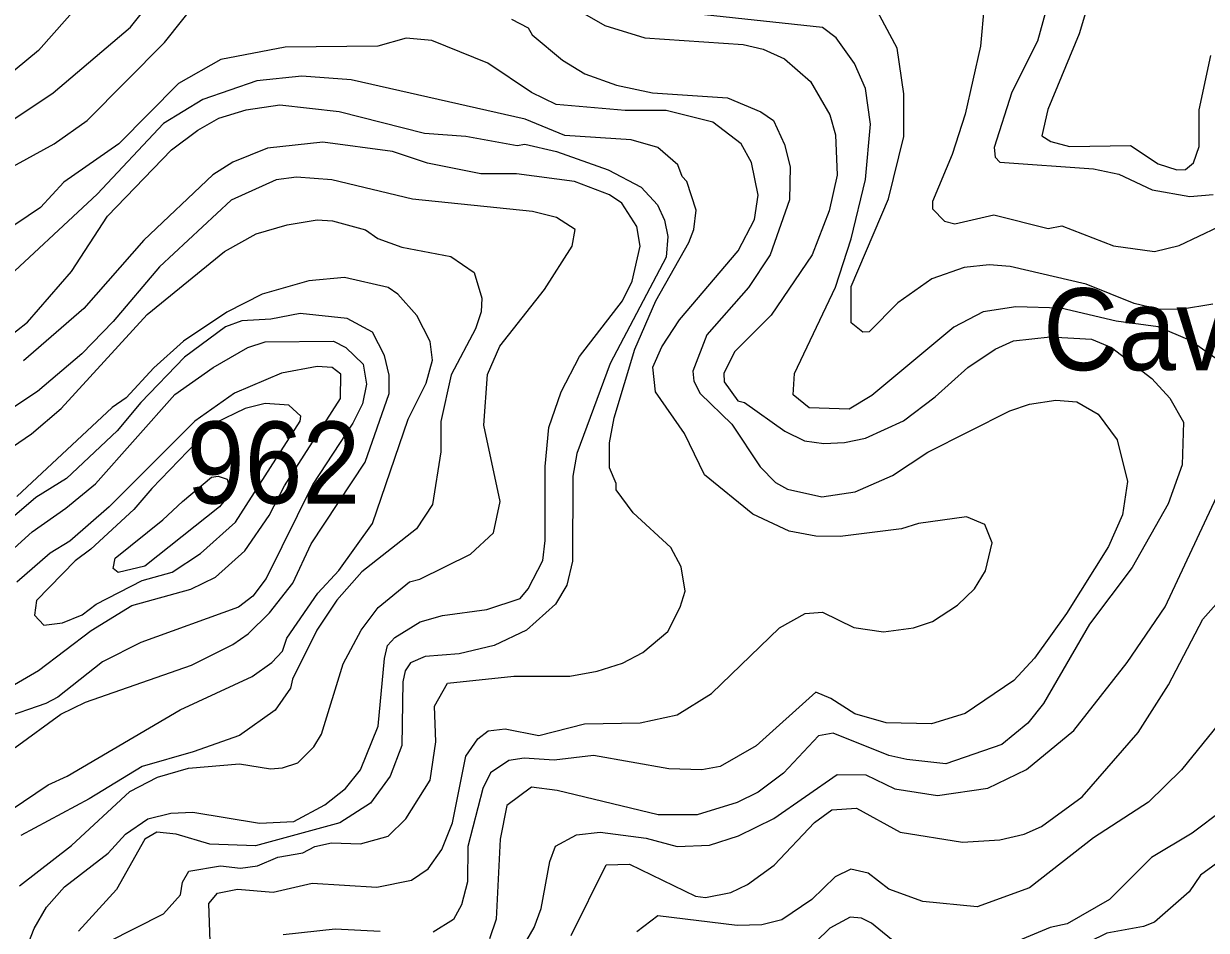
# Model space of a CAD drawing. Extents: x 673.3 to 698.5, y 6984.3 to 7012.3.
# Drawn here: x 686.277 to 687.432, y 6996.366 to 6997.251 of the extents above; entities that cross this region are included whole.
import ezdxf
from ezdxf.enums import TextEntityAlignment as Align

# ---------------------------------------------------------------- set-up
doc = ezdxf.new("R2010")
doc.units = 0
doc.header["$LTSCALE"] = 0.032
doc.layers.add('1', color=7, linetype='Continuous', lineweight=25)
doc.layers.add('2', color=7, linetype='Continuous', lineweight=13)
doc.layers.add('21', color=7, linetype='Continuous')
doc.layers.add('27', color=7, linetype='Continuous')

msp = doc.modelspace()

# ---------------------------------------------------------------- linework, layer by layer
at = {"layer": '1'}
for points in [[(686.1909, 6997.1063), (686.3064, 6997.1831), (686.3819, 6997.2472), (686.4314, 6997.3098)], [(687.323, 6997.2908), (687.3078, 6997.2406), (687.2774, 6997.167), (687.2714, 6997.141), (687.2802, 6997.1355), (687.2986, 6997.1309), (687.358, 6997.1316), (687.385, 6997.1139), (687.4032, 6997.1081), (687.4118, 6997.1084), (687.4195, 6997.1149), (687.425, 6997.1306), (687.4251, 6997.1667), (687.4366, 6997.2195)], [(686.8021, 6997.2733), (686.8448, 6997.2488), (686.8839, 6997.2367), (686.9799, 6997.2304), (686.9994, 6997.2257), (687.0204, 6997.2163), (687.0456, 6997.1943), (687.0644, 6997.1618), (687.0701, 6997.1422), (687.0717, 6997.1028), (687.0639, 6997.068), (687.0473, 6997.0251), (687.0071, 6996.9661), (686.9716, 6996.9305), (686.961, 6996.9091), (686.9615, 6996.901), (686.9748, 6996.8825), (686.9811, 6996.8809), (687.0207, 6996.853), (687.0399, 6996.8435), (687.0588, 6996.841), (687.0787, 6996.8417), (687.0993, 6996.8461), (687.1363, 6996.8631), (687.1674, 6996.8865), (687.1993, 6996.915), (687.2259, 6996.9331), (687.2438, 6996.9412), (687.2796, 6996.9451), (687.3201, 6996.9427), (687.3394, 6996.9347), (687.379, 6996.9042), (687.3964, 6996.8852), (687.4097, 6996.8618), (687.4085, 6996.82), (687.3949, 6996.782), (687.3597, 6996.7197), (687.318, 6996.6644), (687.273, 6996.5871), (687.2579, 6996.568), (687.2323, 6996.5471), (687.1777, 6996.5283), (687.1396, 6996.5323), (687.1222, 6996.5365), (687.0679, 6996.5582), (687.0535, 6996.5557), (687.0194, 6996.519), (686.9946, 6996.5007), (686.9741, 6996.4905), (686.935, 6996.4785), (686.8969, 6996.4785), (686.7982, 6996.5023), (686.7731, 6996.5054), (686.7492, 6996.4875), (686.7427, 6996.4546), (686.7386, 6996.3767), (686.7321, 6996.3573)], [(686.7866, 6996.8184), (686.7901, 6996.8564), (686.8021, 6996.8914), (686.8202, 6996.9259), (686.862, 6996.98), (686.8715, 6996.9992), (686.8794, 6997.0334), (686.8762, 6997.0526), (686.8613, 6997.0756), (686.8493, 6997.0836), (686.8153, 6997.0966), (686.7585, 6997.104), (686.7237, 6997.104), (686.6716, 6997.1146), (686.6376, 6997.1259), (686.5695, 6997.1349), (686.5155, 6997.1292), (686.4816, 6997.1156), (686.4623, 6997.1031), (686.3947, 6997.0394), (686.3361, 6996.9726), (686.2772, 6996.9217)], [(686.2535, 6996.7256), (686.2858, 6996.7545), (686.3187, 6996.7776), (686.3475, 6996.8016), (686.4249, 6996.8887), (686.4625, 6996.915), (686.4962, 6996.9347), (686.5132, 6996.94), (686.5801, 6996.9406), (686.592, 6996.9346), (686.609, 6996.9182), (686.6123, 6996.8989), (686.6082, 6996.8797), (686.5987, 6996.8608), (686.5598, 6996.8011), (686.5141, 6996.709), (686.5012, 6996.6918), (686.4873, 6996.681), (686.392, 6996.6468), (686.3545, 6996.6277), (686.3109, 6996.5932), (686.2992, 6996.587), (686.2558, 6996.5721)], [(686.2788, 6996.3449), (686.2878, 6996.3676), (686.2999, 6996.3884), (686.3174, 6996.4083), (686.3599, 6996.4411), (686.3768, 6996.4596), (686.3986, 6996.4745), (686.421, 6996.4801), (686.4425, 6996.4809), (686.5076, 6996.4704), (686.5411, 6996.4719), (686.5714, 6996.4882), (686.5918, 6996.5043), (686.6062, 6996.5225), (686.6236, 6996.5649), (686.6296, 6996.6311), (686.6328, 6996.6438), (686.6397, 6996.6515), (686.6645, 6996.6669), (686.6865, 6996.6731), (686.7298, 6996.6787), (686.7622, 6996.6895), (686.7701, 6996.6991), (686.7844, 6996.7268), (686.7867, 6996.7461), (686.7866, 6996.8184)], [(687.4624, 6996.4458), (687.4265, 6996.4195), (687.4152, 6996.4033), (687.3815, 6996.3737), (687.3709, 6996.3695), (687.335, 6996.363), (687.3171, 6996.3541), (687.271, 6996.3195), (687.2383, 6996.3007), (687.2079, 6996.2955), (687.1673, 6996.2977), (687.1335, 6996.312), (687.1129, 6996.3295), (687.1084, 6996.3305), (687.1066, 6996.3342), (687.0973, 6996.334), (687.0789, 6996.318)]]:
    msp.add_lwpolyline(points, dxfattribs=at)
at = {"layer": '2'}
for points in [[(686.4192, 6997.3684), (686.2921, 6997.2243), (686.2579, 6997.1961)], [(686.2604, 6997.1075), (686.3073, 6997.1334), (686.3396, 6997.156), (686.415, 6997.2324), (686.4519, 6997.279)], [(687.4534, 6996.9154), (687.4164, 6996.9415), (687.3852, 6996.9549), (687.3441, 6996.9604), (687.2901, 6996.9729), (687.2461, 6996.9744), (687.2143, 6996.9695), (687.1855, 6996.9545), (687.1054, 6996.8876), (687.0835, 6996.8744), (687.0444, 6996.8757), (687.0287, 6996.8883), (687.0301, 6996.9092), (687.0701, 6996.9933), (687.0855, 6997.0405), (687.0993, 6997.0984), (687.1042, 6997.1524), (687.0992, 6997.1873), (687.0886, 6997.2118), (687.0708, 6997.2367), (687.0573, 6997.247), (686.8846, 6997.2655)], [(687.4385, 6996.9768), (687.4069, 6996.9716), (687.3846, 6996.9721), (687.3615, 6996.9775), (687.3149, 6996.9965), (687.2406, 6997.0135), (687.2201, 6997.0152), (687.1956, 6997.0126), (687.164, 6997.0015), (687.1308, 6996.9781), (687.1028, 6996.9497), (687.0968, 6996.9494), (687.0852, 6996.9586), (687.0855, 6996.994), (687.1217, 6997.0798), (687.1368, 6997.1406), (687.1368, 6997.182), (687.1304, 6997.2266), (687.1085, 6997.2674)], [(687.2151, 6997.2685), (687.2117, 6997.2286), (687.1968, 6997.1622), (687.1841, 6997.123), (687.1646, 6997.0771), (687.1646, 6997.0698), (687.1765, 6997.0578), (687.1867, 6997.0552), (687.2245, 6997.064), (687.2777, 6997.0507), (687.2911, 6997.0534), (687.3416, 6997.0339), (687.3814, 6997.0283), (687.4056, 6997.034), (687.4631, 6997.0614)], [(687.2778, 6997.2712), (687.2672, 6997.2337), (687.2423, 6997.1837), (687.225, 6997.1298), (687.2258, 6997.1204), (687.2306, 6997.1155), (687.322, 6997.1088), (687.3468, 6997.1037), (687.3791, 6997.0885), (687.4159, 6997.082), (687.4388, 6997.084)], [(686.7537, 6997.255), (686.7699, 6997.2467), (686.774, 6997.2398), (686.8034, 6997.2149), (686.8252, 6997.2016), (686.8564, 6997.1906), (686.8914, 6997.183), (686.9647, 6997.1781), (686.997, 6997.1645), (687.0096, 6997.1561), (687.0203, 6997.1328), (687.0259, 6997.1109), (687.0253, 6997.0788), (687.0064, 6997.0249), (686.985, 6996.993), (686.9443, 6996.9469), (686.9309, 6996.9114), (686.9316, 6996.9016), (686.9378, 6996.8896), (686.9689, 6996.8599), (686.9965, 6996.818), (687.0114, 6996.8027), (687.0232, 6996.7963), (687.0567, 6996.7889), (687.0894, 6996.7936), (687.1257, 6996.8096), (687.1602, 6996.8323), (687.2403, 6996.8726), (687.2595, 6996.8791), (687.2853, 6996.8833), (687.3057, 6996.8815), (687.3266, 6996.8694), (687.3451, 6996.8445), (687.3551, 6996.8037), (687.3503, 6996.7712), (687.3365, 6996.7402), (687.2956, 6996.6748), (687.2644, 6996.6314), (687.2441, 6996.6094), (687.1966, 6996.5772), (687.1637, 6996.5673), (687.1194, 6996.5681), (687.0888, 6996.577), (687.0654, 6996.5921), (687.0509, 6996.5981), (686.9925, 6996.5459), (686.9574, 6996.5255), (686.9397, 6996.5225), (686.9073, 6996.5234), (686.8338, 6996.5363), (686.7955, 6996.5318), (686.766, 6996.5339), (686.7511, 6996.5314), (686.7333, 6996.5195), (686.7256, 6996.5041), (686.7111, 6996.4474), (686.7109, 6996.4129), (686.7049, 6996.3906), (686.6971, 6996.3762), (686.6772, 6996.3639)], [(686.4602, 6996.3363), (686.4583, 6996.3919), (686.4666, 6996.4019), (686.4862, 6996.406), (686.5211, 6996.4028), (686.5592, 6996.4117), (686.6224, 6996.4077), (686.6562, 6996.4146), (686.6725, 6996.4256), (686.6857, 6996.4445), (686.696, 6996.4706), (686.7092, 6996.5358), (686.7207, 6996.5526), (686.731, 6996.5605), (686.7474, 6996.5624), (686.7803, 6996.5559), (686.8249, 6996.5672), (686.8794, 6996.5681), (686.9156, 6996.576), (686.949, 6996.5968), (687.0155, 6996.6611), (687.0403, 6996.6748), (687.0575, 6996.6764), (687.0878, 6996.6613), (687.117, 6996.6569), (687.1461, 6996.661), (687.1648, 6996.6672), (687.1893, 6996.6831), (687.2058, 6996.6991), (687.2166, 6996.7166), (687.2231, 6996.744), (687.2157, 6996.7619), (687.198, 6996.7692), (687.1511, 6996.7628), (687.1345, 6996.7575), (687.0747, 6996.7501), (687.0508, 6996.7504), (687.0247, 6996.7552), (686.9892, 6996.7718), (686.9421, 6996.8102), (686.9226, 6996.8507), (686.8943, 6996.8912), (686.8918, 6996.9155), (686.9006, 6996.9351), (686.9179, 6996.9617), (686.9751, 6997.0288), (686.9911, 6997.0595), (686.9944, 6997.0832), (686.9882, 6997.1152), (686.9778, 6997.1334), (686.9503, 6997.1544), (686.9048, 6997.1658), (686.8647, 6997.1659), (686.7972, 6997.1719), (686.7734, 6997.1834), (686.7306, 6997.2122), (686.6758, 6997.2341), (686.6508, 6997.2366), (686.6233, 6997.2286), (686.5328, 6997.2277), (686.47, 6997.2156), (686.4286, 6997.1921), (686.3703, 6997.1333), (686.3167, 6997.0958), (686.2938, 6997.0713), (686.2568, 6997.0463)], [(686.8539, 6996.8659), (686.8741, 6996.9328), (686.8945, 6996.9801), (686.927, 6997.0371), (686.9317, 6997.0497), (686.934, 6997.0686), (686.925, 6997.0966), (686.9203, 6997.1016), (686.9161, 6997.1128), (686.8967, 6997.1298), (686.8705, 6997.1373), (686.8058, 6997.1414), (686.767, 6997.1575), (686.5972, 6997.1959), (686.549, 6997.1993), (686.5051, 6997.195), (686.4525, 6997.1767), (686.414, 6997.1532), (686.3491, 6997.0842), (686.2495, 6996.9919)], [(686.2487, 6996.934), (686.2811, 6996.9592), (686.3243, 6997.0089), (686.3593, 6997.0626), (686.4218, 6997.1275), (686.4475, 6997.1468), (686.468, 6997.1584), (686.4946, 6997.1667), (686.5275, 6997.1715), (686.5855, 6997.165), (686.6689, 6997.1438), (686.7091, 6997.1407), (686.7591, 6997.1317), (686.7666, 6997.1331), (686.7976, 6997.1259), (686.848, 6997.1079), (686.8803, 6997.0909), (686.8962, 6997.0737), (686.9032, 6997.0589), (686.9063, 6997.0429), (686.9048, 6997.0227), (686.8499, 6996.9189), (686.8176, 6996.8311), (686.8136, 6996.8089), (686.8132, 6996.7259), (686.8078, 6996.7025), (686.7968, 6996.684), (686.7685, 6996.6588), (686.7368, 6996.6437), (686.7025, 6996.6356), (686.6696, 6996.6331), (686.655, 6996.6269), (686.6498, 6996.6191), (686.6475, 6996.6083), (686.6466, 6996.5462), (686.6354, 6996.5162), (686.6162, 6996.4898), (686.5861, 6996.4706), (686.5038, 6996.4483), (686.4593, 6996.4498), (686.4262, 6996.4597), (686.4074, 6996.4614), (686.3956, 6996.4546), (686.368, 6996.4055), (686.331, 6996.3648)], [(686.2734, 6996.4091), (686.3243, 6996.4486), (686.3811, 6996.5013), (686.408, 6996.5151), (686.4383, 6996.524), (686.4882, 6996.5282), (686.5185, 6996.5234), (686.5301, 6996.5242), (686.545, 6996.5292), (686.5607, 6996.5447), (686.5683, 6996.5573), (686.5894, 6996.6257), (686.6068, 6996.6588), (686.6234, 6996.6808), (686.6542, 6996.7058), (686.6643, 6996.7084), (686.7137, 6996.7328), (686.7361, 6996.7538), (686.7426, 6996.7844), (686.7266, 6996.8588), (686.7304, 6996.9083), (686.7422, 6996.936), (686.786, 6996.9911), (686.8128, 6997.0334), (686.8159, 6997.0499), (686.7976, 6997.0615), (686.7743, 6997.0674), (686.6572, 6997.0795), (686.5784, 6997.0983), (686.5438, 6997.1008), (686.5239, 6997.0983), (686.4802, 6997.0784), (686.4101, 6997.0132), (686.365, 6996.9601), (686.3341, 6996.9283), (686.2909, 6996.8916), (686.269, 6996.8769)], [(686.2405, 6996.8199), (686.2852, 6996.8502), (686.3141, 6996.8749), (686.398, 6996.9669), (686.4734, 6997.0284), (686.5045, 6997.0454), (686.5347, 6997.0542), (686.564, 6997.0591), (686.579, 6997.0583), (686.6112, 6997.0495), (686.6232, 6997.0408), (686.6468, 6997.0324), (686.6944, 6997.0233), (686.7174, 6997.0078), (686.7247, 6996.9826), (686.724, 6996.9693), (686.7187, 6996.9527), (686.6947, 6996.908), (686.6849, 6996.8624), (686.6848, 6996.8328), (686.6767, 6996.7814), (686.661, 6996.7576), (686.6075, 6996.7155), (686.5832, 6996.6881), (686.5637, 6996.6588), (686.5399, 6996.611), (686.5381, 6996.6021), (686.5231, 6996.5807), (686.4881, 6996.556), (686.4429, 6996.5398), (686.393, 6996.5255), (686.3415, 6996.4941), (686.2747, 6996.4583)], [(686.2168, 6996.4507), (686.3014, 6996.5078), (686.3199, 6996.5163), (686.4302, 6996.5808), (686.5006, 6996.6136), (686.5198, 6996.6271), (686.5301, 6996.6383), (686.5343, 6996.6509), (686.5648, 6996.6948), (686.5851, 6996.7168), (686.618, 6996.7627), (686.6529, 6996.8647), (686.6703, 6996.8998), (686.6767, 6996.9223), (686.6743, 6996.9405), (686.6613, 6996.9657), (686.6428, 6996.9865), (686.6334, 6996.9931), (686.5907, 6997.0029), (686.556, 6996.9997), (686.5104, 6996.9866), (686.4758, 6996.9692), (686.4335, 6996.9406), (686.4044, 6996.9147), (686.3775, 6996.8854), (686.364, 6996.8759), (686.2708, 6996.7893)], [(686.2693, 6996.5441), (686.3137, 6996.5767), (686.3379, 6996.5884), (686.4412, 6996.6245), (686.4816, 6996.6447), (686.4965, 6996.6552), (686.5176, 6996.6757), (686.5403, 6996.7044), (686.5582, 6996.7431), (686.6109, 6996.8225), (686.6343, 6996.8898), (686.6343, 6996.9077), (686.6296, 6996.9266), (686.6179, 6996.9494), (686.5933, 6996.963), (686.5475, 6996.9679), (686.5187, 6996.9623), (686.4905, 6996.9605), (686.4746, 6996.9548), (686.4345, 6996.9252), (686.3919, 6996.8809), (686.3688, 6996.8531), (686.3193, 6996.8067), (686.2894, 6996.7881), (686.2383, 6996.7446)], [(686.2174, 6996.5759), (686.2921, 6996.6193), (686.3432, 6996.6582), (686.3832, 6996.6826), (686.4406, 6996.6986), (686.4647, 6996.7105), (686.4935, 6996.736), (686.517, 6996.7707), (686.5322, 6996.7997), (686.5868, 6996.8847), (686.587, 6996.9084), (686.5787, 6996.915), (686.564, 6996.9159), (686.5291, 6996.9095), (686.4832, 6996.8899), (686.4446, 6996.8627), (686.3609, 6996.7792), (686.3224, 6996.7454), (686.3033, 6996.7339), (686.2708, 6996.7054)], [(686.3594, 6996.3541), (686.414, 6996.3819), (686.4306, 6996.4004), (686.4326, 6996.4128), (686.4388, 6996.4233), (686.4696, 6996.4288), (686.4892, 6996.4264), (686.5058, 6996.4285), (686.5257, 6996.437), (686.55, 6996.4414), (686.5617, 6996.4475), (686.5781, 6996.451), (686.6063, 6996.4502), (686.6333, 6996.4575), (686.6507, 6996.4744), (686.6744, 6996.5122), (686.6799, 6996.5498), (686.6784, 6996.5844), (686.6912, 6996.607), (686.7559, 6996.6137), (686.8106, 6996.6138), (686.8375, 6996.6188), (686.8621, 6996.6266), (686.8818, 6996.6368), (686.9062, 6996.6574), (686.9185, 6996.6811), (686.9233, 6996.6966), (686.9194, 6996.7204), (686.9094, 6996.7393), (686.8725, 6996.7731), (686.856, 6996.7956), (686.8559, 6996.8019), (686.8494, 6996.8172), (686.8494, 6996.8416), (686.8539, 6996.8659)], [(687.3548, 6996.627), (687.3919, 6996.6816), (687.4424, 6996.7891)], [(686.8121, 6996.3607), (686.846, 6996.4296), (686.8689, 6996.4304), (686.9335, 6996.399), (686.9432, 6996.3979), (686.9677, 6996.4025), (686.984, 6996.4103), (687.0103, 6996.4293), (687.0495, 6996.4708), (687.0664, 6996.4834), (687.0904, 6996.485), (687.1331, 6996.4614), (687.194, 6996.4517), (687.2305, 6996.454), (687.2543, 6996.4596), (687.271, 6996.467), (687.3108, 6996.4961), (687.3655, 6996.5589), (687.3953, 6996.6053), (687.4286, 6996.6694), (687.4544, 6996.6984)], [(686.7616, 6996.3436), (686.7759, 6996.3685), (686.7827, 6996.3869), (686.791, 6996.4328), (686.7967, 6996.4477), (686.8171, 6996.4589), (686.8403, 6996.4614), (686.8852, 6996.4557), (686.9156, 6996.4476), (686.9469, 6996.4488), (686.9754, 6996.4579), (687.01, 6996.4749), (687.0717, 6996.5177), (687.0996, 6996.5176), (687.1281, 6996.5038), (687.1695, 6996.4972), (687.2189, 6996.5046), (687.2566, 6996.5226), (687.3027, 6996.5606), (687.3548, 6996.627)], [(687.4592, 6996.5858), (687.4078, 6996.5223), (687.3757, 6996.4909), (687.322, 6996.4559), (687.2594, 6996.4073), (687.2082, 6996.3888), (687.1553, 6996.3939), (687.1221, 6996.4058), (687.1018, 6996.4215), (687.0851, 6996.4255), (687.0697, 6996.4178), (687.0468, 6996.3958), (687.0176, 6996.3759), (686.998, 6996.3711), (686.9741, 6996.3703), (686.8965, 6996.3798), (686.8762, 6996.3643)], [(687.4485, 6996.4832), (687.4181, 6996.4607), (687.3787, 6996.4368), (687.3375, 6996.3957), (687.2963, 6996.3721), (687.2797, 6996.3686), (687.2172, 6996.3425)], [(687.1318, 6996.3508), (687.1051, 6996.3726), (687.0953, 6996.3775), (687.0844, 6996.3784), (687.0645, 6996.3677), (687.0235, 6996.3277)], [(686.6255, 6996.3646), (686.5817, 6996.3669), (686.5308, 6996.3614)]]:
    msp.add_lwpolyline(points, dxfattribs=at)
for points in [[(686.5474, 6996.8627), (686.5479, 6996.8677), (686.5365, 6996.8783), (686.5133, 6996.88), (686.4937, 6996.8751), (686.464, 6996.8607), (686.4025, 6996.7968), (686.3849, 6996.7764), (686.343, 6996.7376), (686.3276, 6996.7263), (686.2899, 6996.6875), (686.2879, 6996.6732), (686.2971, 6996.6635), (686.3154, 6996.6659), (686.3345, 6996.6735), (686.3482, 6996.684), (686.3931, 6996.7072), (686.4224, 6996.7152), (686.45, 6996.7336), (686.4843, 6996.7641)], [(686.4133, 6996.7665), (686.4325, 6996.7844), (686.4607, 6996.808), (686.4673, 6996.8089), (686.4763, 6996.8062), (686.4796, 6996.7928), (686.4688, 6996.7792), (686.3956, 6996.7211), (686.3696, 6996.7148), (686.365, 6996.7189), (686.3668, 6996.7291)]]:
    msp.add_lwpolyline(points, close=True, dxfattribs=at)

# ---------------------------------------------------------------- texts
at = {"layer": '21', "width": 0.95}
msp.add_text('962', height=0.08, dxfattribs=at).set_placement((686.4366, 6996.7823))
at = {"layer": '27', "width": 0.95}
msp.add_text('Cavalo Branco', height=0.08, dxfattribs=at).set_placement((687.606, 6996.9124), align=Align.CENTER)

doc.saveas('drawing.dxf')
